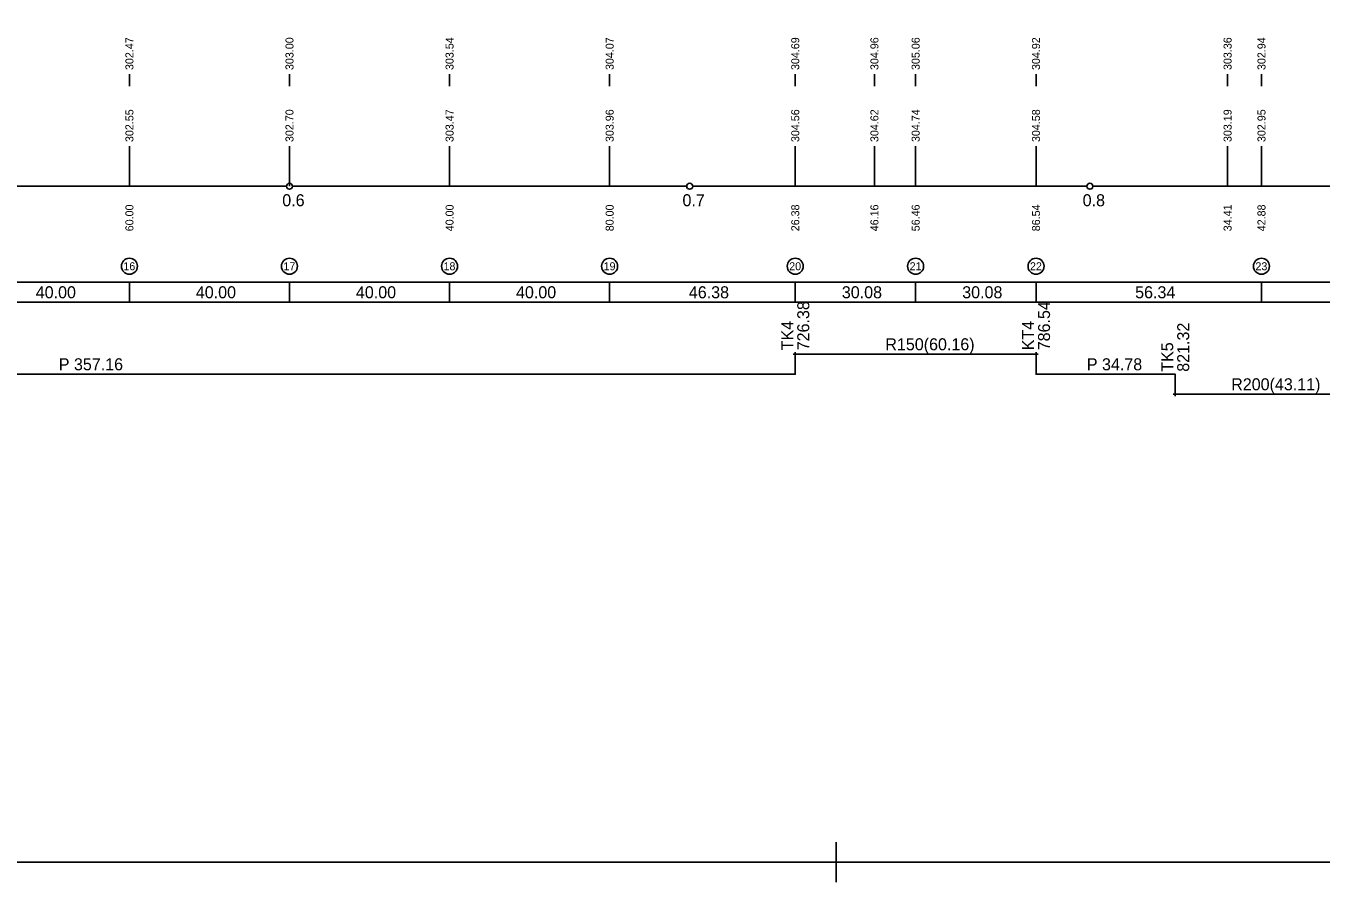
# Model space of a CAD drawing. Extents: x -39 to 1232, y -119 to 485.
# Drawn here: x 604.1 to 927.8, y -118.9 to 95.1 of the extents above; entities that cross this region are included whole.
import ezdxf

# ---------------------------------------------------------------- set-up
doc = ezdxf.new("R2010")
doc.units = 0
for name, color, linetype in [('ramecek', 7, 'Continuous'), ('SESTAVY_REZU_PO', 7, 'Continuous'), ('SMEROVE_POMERY', 7, 'Continuous'), ('SMEROVE_POMERY_KOD', 7, 'Continuous'), ('SVK_STAT', 7, 'Continuous'), ('TABULKY', 7, 'Continuous')]:
    doc.layers.add(name, color=color, linetype=linetype)

msp = doc.modelspace()

# ---------------------------------------------------------------- linework, layer by layer
for p, q in [((806.58, -108.92), (806.58, -118.92)), ((806.58, -108.92), (806.58, -118.92)), ((806.58, -108.92), (806.58, -118.92)), ((806.58, -108.92), (806.58, -118.92)), ((806.58, -108.92), (806.58, -118.92)), ((806.58, -108.92), (806.58, -118.92)), ((806.58, -108.92), (806.58, -118.92)), ((806.58, -108.92), (806.58, -118.92)), ((806.58, -108.92), (806.58, -118.92)), ((806.58, -108.92), (806.58, -118.92)), ((806.58, -108.92), (806.58, -118.92)), ((806.58, -108.92), (806.58, -118.92)), ((806.58, -108.92), (806.58, -118.92)), ((806.58, -108.92), (806.58, -118.92)), ((806.58, -108.92), (806.58, -118.92)), ((806.58, -108.92), (806.58, -118.92)), ((811.58, -113.92), (801.58, -113.92)), ((811.58, -113.92), (801.58, -113.92)), ((811.58, -113.92), (801.58, -113.92)), ((811.58, -113.92), (801.58, -113.92)), ((811.58, -113.92), (801.58, -113.92)), ((811.58, -113.92), (801.58, -113.92)), ((811.58, -113.92), (801.58, -113.92)), ((811.58, -113.92), (801.58, -113.92)), ((811.58, -113.92), (801.58, -113.92)), ((811.58, -113.92), (801.58, -113.92)), ((811.58, -113.92), (801.58, -113.92)), ((811.58, -113.92), (801.58, -113.92)), ((811.58, -113.92), (801.58, -113.92)), ((811.58, -113.92), (801.58, -113.92)), ((811.58, -113.92), (801.58, -113.92)), ((811.58, -113.92), (801.58, -113.92))]:
    msp.add_line(p, q)
at = {"layer": 'ramecek'}
msp.add_lwpolyline([(-34.42, -113.92), (1226.58, -113.92), (1226.58, 480.08), (-34.42, 480.08)], close=True, dxfattribs=at)
at = {"layer": 'SESTAVY_REZU_PO'}
for points in [[(570.75, 55), (669.25, 55)], [(670.75, 55), (769.25, 55)], [(770.75, 55), (869.25, 55)], [(870.75, 55), (969.25, 55)], [(630, 26), (630, 31)], [(670, 26), (670, 31)], [(710, 26), (710, 31)], [(750, 26), (750, 31)], [(796.38, 26), (796.38, 31)], [(826.46, 26), (826.46, 31)], [(856.54, 26), (856.54, 31)], [(912.88, 26), (912.88, 31)]]:
    msp.add_lwpolyline(points, dxfattribs=at)
for centre in [(670, 55), (770, 55), (870, 55)]:
    msp.add_circle(centre, 0.75, dxfattribs=at)
at = {"layer": 'SMEROVE_POMERY'}
msp.add_lwpolyline([(439.21, 8), (796.38, 8), (796.38, 13), (796.38, 8), (796.38, 13), (856.54, 13), (856.54, 8), (856.54, 13), (856.54, 8), (891.32, 8), (891.32, 3), (934.43, 3)], dxfattribs=at)
at = {"layer": 'SMEROVE_POMERY_KOD'}
for points in [[(795.88, 13), (796.88, 13)], [(795.88, 13), (796.88, 13)], [(796.38, 12.5), (796.38, 13.5)], [(796.38, 12.5), (796.38, 13.5)], [(856.04, 13), (857.04, 13)], [(856.04, 13), (857.04, 13)], [(856.54, 12.5), (856.54, 13.5)], [(856.54, 12.5), (856.54, 13.5)], [(891.32, 2.5), (891.32, 3.5)], [(890.82, 3), (891.82, 3)]]:
    msp.add_lwpolyline(points, dxfattribs=at)
at = {"layer": 'SVK_STAT'}
for points in [[(630, 80), (630, 83)], [(670, 80), (670, 83)], [(710, 80), (710, 83)], [(750, 80), (750, 83)], [(796.38, 80), (796.38, 83)], [(816.16, 80), (816.16, 83)], [(826.46, 80), (826.46, 83)], [(856.54, 80), (856.54, 83)], [(904.41, 80), (904.41, 83)], [(912.88, 80), (912.88, 83)], [(630, 55), (630, 65)], [(670, 55), (670, 65)], [(710, 55), (710, 65)], [(750, 55), (750, 65)], [(796.38, 55), (796.38, 65)], [(816.16, 55), (816.16, 65)], [(826.46, 55), (826.46, 65)], [(856.54, 55), (856.54, 65)], [(904.41, 55), (904.41, 65)], [(912.88, 55), (912.88, 65)]]:
    msp.add_lwpolyline(points, dxfattribs=at)
for centre in [(630, 35), (670, 35), (710, 35), (750, 35), (796.38, 35), (826.46, 35), (856.54, 35), (912.88, 35)]:
    msp.add_circle(centre, 2, dxfattribs=at)
at = {"layer": 'TABULKY'}
msp.add_lwpolyline([(70, 26), (1165.19, 26), (1165.19, 31), (70, 31), (70, 26)], dxfattribs=at)

# ---------------------------------------------------------------- texts
at = {"layer": 'SESTAVY_REZU_PO'}
for s, p in [('0.6', (668.2, 50)), ('0.7', (768.2, 50)), ('0.8', (868.2, 50)), ('40.00', (606.6, 27)), ('40.00', (646.6, 27)), ('40.00', (686.6, 27)), ('40.00', (726.6, 27)), ('46.38', (769.79, 27)), ('30.08', (808.02, 27)), ('30.08', (838.1, 27)), ('56.34', (881.31, 27))]:
    msp.add_text(s, height=3, dxfattribs=at).set_placement(p)
at = {"layer": 'SMEROVE_POMERY'}
for s, p in [('R150(60.16)', (818.89, 14)), ('P 357.16', (612.35, 9)), ('P 34.78', (869.24, 9)), ('R200(43.11)', (905.31, 4))]:
    msp.add_text(s, height=3, dxfattribs=at).set_placement(p)
at = {"layer": 'SMEROVE_POMERY_KOD'}
for s, p in [('726.38', (799.88, 14)), ('726.38', (799.88, 14)), ('786.54', (860.04, 14)), ('786.54', (860.04, 14)), ('TK4', (795.88, 14)), ('TK4', (795.88, 14)), ('KT4', (856.04, 14)), ('KT4', (856.04, 14)), ('821.32', (894.82, 8.63)), ('TK5', (890.82, 8.63))]:
    msp.add_text(s, height=3, rotation=90, dxfattribs=at).set_placement(p)
at = {"layer": 'SVK_STAT'}
for s, p in [(' 302.47', (631, 83.3)), (' 303.00', (671, 83.3)), (' 303.54', (711, 83.3)), (' 304.07', (751, 83.3)), (' 304.69', (797.38, 83.3)), (' 304.96', (817.16, 83.3)), (' 305.06', (827.46, 83.3)), (' 304.92', (857.54, 83.3)), (' 303.36', (905.41, 83.3)), (' 302.94', (913.88, 83.3)), (' 302.55', (631, 65.3)), (' 302.70', (671, 65.3)), (' 303.47', (711, 65.3)), (' 303.96', (751, 65.3)), (' 304.56', (797.38, 65.3)), (' 304.62', (817.16, 65.3)), (' 304.74', (827.46, 65.3)), (' 304.58', (857.54, 65.3)), (' 303.19', (905.41, 65.3)), (' 302.95', (913.88, 65.3)), (' 60.00', (631, 43)), (' 40.00', (711, 43)), (' 80.00', (751, 43)), (' 26.38', (797.38, 43)), (' 46.16', (817.16, 43)), (' 56.46', (827.46, 43)), (' 86.54', (857.54, 43)), (' 34.41', (905.41, 43)), (' 42.88', (913.88, 43))]:
    msp.add_text(s, height=2, rotation=90, dxfattribs=at).set_placement(p)
for s, p in [('16', (628.49, 34)), ('17', (668.49, 34)), ('18', (708.49, 34)), ('19', (748.49, 34)), ('20', (794.87, 34)), ('21', (824.95, 34)), ('22', (855.03, 34)), ('23', (911.37, 34))]:
    msp.add_text(s, height=2, dxfattribs=at).set_placement(p)

doc.saveas('drawing.dxf')
